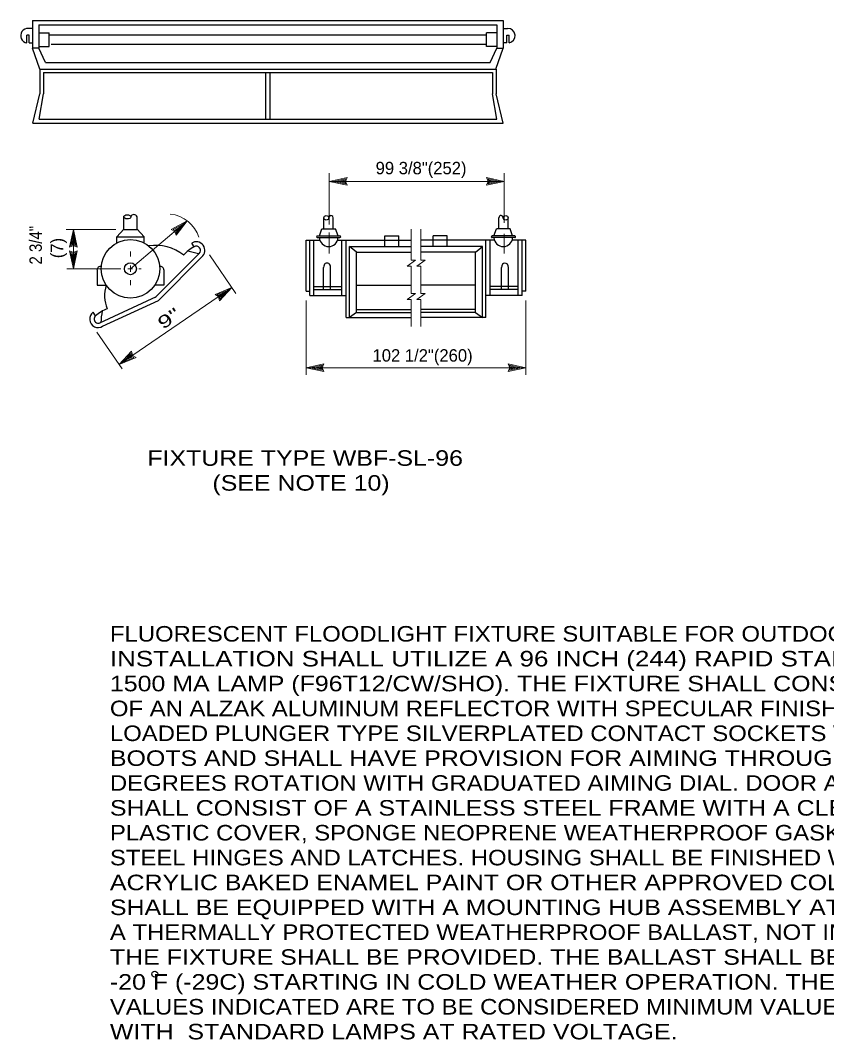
# Model space of a CAD drawing. Extents: x -39.6 to 16.1, y -17.6 to 34.
# Drawn here: x 2.33 to 8.82, y 15.9 to 24.1 of the extents above; entities that cross this region are included whole.
import ezdxf
from ezdxf.enums import TextEntityAlignment as Align

# ---------------------------------------------------------------- set-up
doc = ezdxf.new("R2010")
doc.units = 0
doc.header["$LTSCALE"] = 0.05
doc.layers.add('1', color=7, linetype='Continuous', lineweight=13)

msp = doc.modelspace()

# ---------------------------------------------------------------- linework, layer by layer
at = {"layer": '1', "lineweight": 25}
for p, q in [((2.43279, 24.02942), (2.39679, 24.02942)), ((2.43279, 24.09542), (6.22079, 24.09542)), ((2.43279, 24.09542), (2.43279, 23.87242)), ((2.48379, 24.05842), (6.16979, 24.05842)), ((6.22079, 24.09542), (6.22079, 23.87242)), ((6.22079, 24.02942), (6.25679, 24.02942)), ((2.38579, 23.91542), (2.38579, 23.97542)), ((2.48379, 23.99442), (2.56579, 23.99442)), ((6.08779, 23.97742), (2.56579, 23.97742)), ((6.16979, 23.99442), (6.08779, 23.99442)), ((6.26779, 23.91542), (6.26779, 23.97542)), ((2.40379, 23.91542), (2.43279, 23.91542)), ((2.49179, 23.70342), (2.43279, 23.87242)), ((2.53679, 23.75642), (2.48379, 23.87242)), ((6.08779, 23.90142), (2.58079, 23.90142)), ((6.11679, 23.75642), (6.16979, 23.87242)), ((6.16179, 23.70342), (6.22079, 23.87242)), ((6.24979, 23.91542), (6.22079, 23.91542)), ((2.48979, 23.70342), (2.48979, 23.50442)), ((2.49179, 23.70342), (6.16379, 23.70342)), ((2.53679, 23.75642), (6.11679, 23.75642)), ((6.16379, 23.70342), (6.16379, 23.50442)), ((2.51979, 23.67542), (6.13379, 23.67542)), ((2.51979, 23.67542), (2.51979, 23.50442)), ((4.30979, 23.30042), (4.30979, 23.67542)), ((4.34579, 23.30042), (4.34579, 23.67542)), ((6.13379, 23.67542), (6.13379, 23.50442)), ((2.43379, 23.26742), (2.48979, 23.50442)), ((2.48479, 23.30042), (2.51979, 23.50442)), ((6.21979, 23.26742), (6.16379, 23.50442)), ((2.43379, 23.26742), (6.21979, 23.26742)), ((4.77679, 22.41842), (4.77679, 22.50742)), ((4.85179, 22.41842), (4.85179, 22.50742)), ((6.18579, 22.41842), (6.18579, 22.50742)), ((6.26079, 22.41842), (6.26079, 22.50742)), ((3.16479, 22.41442), (3.27379, 22.41442)), ((4.74079, 22.36142), (4.75979, 22.41842)), ((4.75979, 22.41842), (4.87179, 22.41842)), ((4.89179, 22.36142), (4.87179, 22.41842)), ((6.14579, 22.36142), (6.16579, 22.41842)), ((6.27779, 22.41842), (6.16579, 22.41842)), ((6.29679, 22.36142), (6.27779, 22.41842)), ((3.10979, 22.35542), (3.32979, 22.35542)), ((3.73379, 22.27442), (3.71379, 22.30342)), ((4.63379, 21.91742), (4.63379, 22.32842)), ((4.63379, 22.32842), (4.74079, 22.32842)), ((4.66479, 21.88142), (4.66479, 22.32842)), ((4.69579, 21.88142), (4.69579, 22.32842)), ((4.72379, 22.36142), (4.90679, 22.36142)), ((4.72379, 22.34842), (4.90679, 22.34842)), ((4.88579, 22.32842), (5.47979, 22.32842)), ((4.92279, 21.88142), (4.92279, 22.33042)), ((4.95679, 21.70442), (4.95679, 22.33042)), ((5.26879, 22.27742), (5.26879, 22.36142)), ((5.26879, 22.36142), (5.38079, 22.36142)), ((5.38079, 22.27742), (5.38079, 22.36142)), ((6.15179, 22.32842), (5.55779, 22.32842)), ((5.65679, 22.27742), (5.65679, 22.36142)), ((5.76879, 22.36142), (5.65679, 22.36142)), ((5.76879, 22.27742), (5.76879, 22.36142)), ((6.08079, 21.70442), (6.08079, 22.33042)), ((6.11479, 21.88142), (6.11479, 22.33042)), ((6.31379, 22.36142), (6.13079, 22.36142)), ((6.31379, 22.34842), (6.13079, 22.34842)), ((6.40379, 22.32842), (6.29679, 22.32842)), ((6.34179, 21.88142), (6.34179, 22.32842)), ((6.37279, 21.88142), (6.37279, 22.32842)), ((6.40379, 21.91742), (6.40379, 22.32842)), ((3.77479, 22.22242), (3.41979, 21.86642)), ((5.03979, 22.23042), (4.98379, 22.27742)), ((5.99779, 22.23042), (6.05379, 22.27742)), ((3.79479, 22.19242), (3.44479, 21.84242)), ((4.77479, 21.93142), (4.77479, 22.10842)), ((4.83079, 21.93142), (4.83079, 22.10842)), ((6.20679, 21.93142), (6.20679, 22.10842)), ((6.26279, 21.93142), (6.26279, 22.10842)), ((4.63379, 21.91742), (4.66479, 21.91742)), ((4.69579, 21.95442), (4.92279, 21.95442)), ((4.69579, 21.93142), (4.92279, 21.93142)), ((5.03979, 21.96542), (5.47979, 21.96542)), ((5.99779, 21.96542), (5.55779, 21.96542)), ((6.34179, 21.95442), (6.11479, 21.95442)), ((6.34179, 21.93142), (6.11479, 21.93142)), ((6.40379, 21.91742), (6.37279, 21.91742)), ((2.97379, 21.66242), (3.42979, 21.87342)), ((2.99579, 21.63442), (3.44479, 21.84242)), ((4.66479, 21.88142), (4.95679, 21.88142)), ((6.37279, 21.88142), (6.08079, 21.88142)), ((2.93979, 21.71842), (2.91979, 21.74742)), ((5.03979, 21.74642), (4.98379, 21.70442)), ((5.03979, 21.76942), (5.47979, 21.76942)), ((5.03979, 21.74642), (5.47979, 21.74642)), ((5.99779, 21.76942), (5.55779, 21.76942)), ((5.99779, 21.74642), (5.55779, 21.74642)), ((5.99779, 21.74642), (6.05379, 21.70442)), ((4.95679, 21.70442), (5.47979, 21.70442)), ((6.08079, 21.70442), (5.55779, 21.70442))]:
    msp.add_line(p, q, dxfattribs=at)
at = {"layer": '1'}
for p, q in [((4.82079, 22.45442), (4.82079, 22.86642)), ((4.82079, 22.80042), (4.96479, 22.83142)), ((4.82079, 22.80042), (6.22979, 22.80042)), ((4.82079, 22.80042), (4.96479, 22.76942)), ((4.85779, 22.80042), (4.95179, 22.82042)), ((4.85779, 22.80042), (4.95179, 22.78042)), ((4.89379, 22.80042), (4.93879, 22.81042)), ((4.89379, 22.80042), (4.93879, 22.79142)), ((4.93879, 22.81042), (4.93479, 22.80042)), ((4.93479, 22.80042), (4.93879, 22.79142)), ((4.95179, 22.82042), (4.94279, 22.80042)), ((4.94279, 22.80042), (4.95179, 22.78042)), ((6.22979, 22.80042), (6.08579, 22.83142)), ((6.22979, 22.80042), (6.08579, 22.76942)), ((6.19279, 22.80042), (6.09879, 22.82042)), ((6.10779, 22.80042), (6.09879, 22.82042)), ((6.19279, 22.80042), (6.09879, 22.78042)), ((6.09879, 22.78042), (6.10779, 22.80042)), ((6.15679, 22.80042), (6.11179, 22.80942)), ((6.11579, 22.80042), (6.11179, 22.80942)), ((6.15679, 22.80042), (6.11179, 22.79042)), ((6.11179, 22.79042), (6.11579, 22.80042)), ((6.22979, 22.46742), (6.22979, 22.86642)), ((3.21979, 22.09742), (3.67779, 22.48242)), ((3.67779, 22.48242), (3.54779, 22.41342)), ((3.67779, 22.48242), (3.58779, 22.36642)), ((3.10279, 22.41442), (2.70379, 22.41442)), ((2.76079, 22.41442), (2.72979, 22.27042)), ((2.76079, 22.09742), (2.76079, 22.41442)), ((2.76079, 22.41442), (2.79179, 22.27042)), ((3.64979, 22.45842), (3.56479, 22.41342)), ((3.58479, 22.40342), (3.56479, 22.41342)), ((3.62179, 22.43542), (3.58179, 22.41342)), ((3.59079, 22.40942), (3.58179, 22.41342)), ((3.59079, 22.38242), (3.58479, 22.40342)), ((3.64979, 22.45842), (3.59079, 22.38242)), ((3.59379, 22.39842), (3.59079, 22.40942)), ((3.62179, 22.43542), (3.59379, 22.39842)), ((4.82079, 22.21942), (4.82079, 22.38842)), ((5.47979, 22.16642), (5.47979, 22.41642)), ((5.55779, 22.16642), (5.55779, 22.41642)), ((2.76079, 22.37742), (2.74079, 22.28342)), ((2.76079, 22.34142), (2.75179, 22.29642)), ((2.76079, 22.37742), (2.78079, 22.28342)), ((2.76079, 22.34142), (2.77079, 22.29642)), ((6.22979, 22.21942), (6.22979, 22.37942)), ((2.76079, 22.09742), (2.72979, 22.24142)), ((2.76079, 22.29242), (2.74079, 22.28342)), ((2.76079, 22.13442), (2.74079, 22.22842)), ((2.74079, 22.22842), (2.76079, 22.21942)), ((2.76079, 22.30042), (2.75179, 22.29642)), ((2.77079, 22.29642), (2.76079, 22.30042)), ((2.78079, 22.28342), (2.76079, 22.29242)), ((2.76079, 22.09742), (2.79179, 22.24142)), ((2.76079, 22.13442), (2.78079, 22.22842)), ((2.76079, 22.21942), (2.78079, 22.22842)), ((3.21979, 22.19542), (3.21979, 22.23542)), ((2.76079, 22.17042), (2.75079, 22.21542)), ((2.75079, 22.21542), (2.76079, 22.21142)), ((2.76079, 22.17042), (2.76979, 22.21542)), ((2.76079, 22.21142), (2.76979, 22.21542)), ((3.85779, 22.20842), (4.06979, 21.89842)), ((5.44679, 22.11842), (5.51379, 22.16642)), ((5.47979, 22.16642), (5.51379, 22.16642)), ((5.52479, 22.11842), (5.59179, 22.16642)), ((5.55779, 22.16642), (5.59179, 22.16642)), ((3.14179, 22.09742), (2.70779, 22.09742)), ((3.23579, 22.09742), (3.19979, 22.09742)), ((3.21979, 22.07142), (3.21979, 22.12442)), ((3.30579, 22.09742), (3.28879, 22.09742)), ((5.44679, 22.11842), (5.47979, 22.11842)), ((5.47979, 21.89942), (5.47979, 22.11842)), ((5.52479, 22.11842), (5.55779, 22.11842)), ((5.55779, 21.89942), (5.55779, 22.11842)), ((3.21979, 21.96542), (3.21979, 22.00542)), ((3.12879, 21.32642), (4.03679, 21.94642)), ((4.03679, 21.94642), (3.90079, 21.89042)), ((4.00579, 21.92542), (3.91779, 21.88942)), ((3.97679, 21.90542), (3.93379, 21.88742)), ((4.03679, 21.94642), (3.93579, 21.83942)), ((4.00579, 21.92542), (3.93979, 21.85642)), ((3.97679, 21.90542), (3.94479, 21.87142)), ((5.44679, 21.85142), (5.51379, 21.89942)), ((5.47979, 21.89942), (5.51379, 21.89942)), ((5.52479, 21.85142), (5.59179, 21.89942)), ((5.55779, 21.89942), (5.59179, 21.89942)), ((3.93579, 21.87742), (3.91779, 21.88942)), ((3.94279, 21.88242), (3.93379, 21.88742)), ((3.93979, 21.85642), (3.93579, 21.87742)), ((3.94479, 21.87142), (3.94279, 21.88242)), ((4.63379, 21.84242), (4.63379, 21.24442)), ((5.44679, 21.85142), (5.47979, 21.85142)), ((5.47979, 21.63242), (5.47979, 21.85142)), ((5.52479, 21.85142), (5.55779, 21.85142)), ((5.55779, 21.63242), (5.55779, 21.85142)), ((6.40379, 21.84242), (6.40379, 21.24442)), ((2.94979, 21.58842), (3.15279, 21.29142)), ((3.12879, 21.32642), (3.22979, 21.43342)), ((3.15979, 21.34742), (3.22579, 21.41642)), ((3.18879, 21.36742), (3.22079, 21.40142)), ((3.22079, 21.40142), (3.22279, 21.39042)), ((3.22579, 21.41642), (3.22979, 21.39542)), ((3.12879, 21.32642), (3.26479, 21.38242)), ((3.15979, 21.34742), (3.24779, 21.38342)), ((3.18879, 21.36742), (3.23179, 21.38542)), ((3.22279, 21.39042), (3.23179, 21.38542)), ((3.22979, 21.39542), (3.24779, 21.38342)), ((4.63379, 21.30142), (4.77779, 21.33242)), ((4.67079, 21.30142), (4.76479, 21.32142)), ((4.76479, 21.32142), (4.75579, 21.30142)), ((6.40379, 21.30142), (6.25979, 21.33242)), ((6.36679, 21.30142), (6.27279, 21.32142)), ((6.28179, 21.30142), (6.27279, 21.32142)), ((4.63379, 21.30142), (6.40379, 21.30142)), ((4.63379, 21.30142), (4.77779, 21.27042)), ((4.67079, 21.30142), (4.76479, 21.28142)), ((4.70679, 21.30142), (4.75179, 21.31142)), ((4.70679, 21.30142), (4.75179, 21.29242)), ((4.75179, 21.31142), (4.74779, 21.30142)), ((4.74779, 21.30142), (4.75179, 21.29242)), ((4.75579, 21.30142), (4.76479, 21.28142)), ((6.40379, 21.30142), (6.25979, 21.27042)), ((6.36679, 21.30142), (6.27279, 21.28142)), ((6.27279, 21.28142), (6.28179, 21.30142)), ((6.33079, 21.30142), (6.28579, 21.31042)), ((6.28979, 21.30142), (6.28579, 21.31042)), ((6.33079, 21.30142), (6.28579, 21.29142)), ((6.28579, 21.29142), (6.28979, 21.30142))]:
    msp.add_line(p, q, dxfattribs=at)
at = {"layer": '1', "lineweight": 25}
for points in [[(2.48379, 24.05842), (2.48379, 23.87242), (2.43279, 23.87242)], [(6.16979, 24.05842), (6.16979, 23.87242), (6.22079, 23.87242)], [(2.40379, 23.91542), (2.40379, 23.97542), (2.38579, 23.97542)], [(2.48379, 23.88642), (2.56579, 23.88642), (2.56579, 23.99442)], [(6.16979, 23.88642), (6.08779, 23.88642), (6.08779, 23.99442)], [(6.24979, 23.91542), (6.24979, 23.97542), (6.26779, 23.97542)], [(2.48479, 23.30042), (6.16879, 23.30042), (6.13379, 23.50442)], [(3.10979, 22.30542), (3.10979, 22.35542), (3.16579, 22.41542), (3.16579, 22.51542)], [(3.32979, 22.30542), (3.32979, 22.35542), (3.27379, 22.41542), (3.27379, 22.51542)], [(4.98379, 21.70442), (4.98379, 22.27742), (5.47979, 22.27742)], [(5.03979, 21.74642), (5.03979, 22.23042), (5.47979, 22.23042)], [(6.05379, 21.70442), (6.05379, 22.27742), (5.55779, 22.27742)], [(5.99779, 21.74642), (5.99779, 22.23042), (5.55779, 22.23042)], [(2.95079, 22.08842), (2.95079, 21.96442), (3.02479, 21.96442)], [(3.48879, 22.08842), (3.48879, 21.96442), (3.41479, 21.96442)]]:
    msp.add_lwpolyline(points, dxfattribs=at)
at = {"layer": '1'}
for points in [[(4.96479, 22.83142), (4.95079, 22.80042), (4.96479, 22.76942)], [(6.08579, 22.76942), (6.09979, 22.80042), (6.08579, 22.83142)], [(3.58779, 22.36642), (3.57779, 22.39842), (3.54779, 22.41342)], [(2.79179, 22.27042), (2.76079, 22.28442), (2.72979, 22.27042)], [(2.72979, 22.24142), (2.76079, 22.22742), (2.79179, 22.24142)], [(3.93579, 21.83942), (3.92979, 21.87342), (3.90079, 21.89042)], [(3.22979, 21.43342), (3.23579, 21.39942), (3.26479, 21.38242)], [(4.77779, 21.33242), (4.76379, 21.30142), (4.77779, 21.27042)], [(6.25979, 21.27042), (6.27379, 21.30142), (6.25979, 21.33242)]]:
    msp.add_lwpolyline(points, dxfattribs=at)
at = {"layer": '1', "lineweight": 25}
for centre, radius in [((3.21979, 22.09742), 0.23567), ((3.21979, 22.09742), 0.04804), ((3.41579, 16.42342), 0.024)]:
    msp.add_circle(centre, radius, dxfattribs=at)
for centre, radius, start, end in [((3.24845, 22.50678), 0.02677, 18.82841, 163.4182), ((4.81584, 22.35119), 0.0751, 182.11351, 356.35869), ((6.22174, 22.35119), 0.0751, 183.64131, 357.88649), ((3.42373, 21.92785), 0.35813, 51.06477, 99.14828), ((3.86715, 22.01905), 0.28818, 117.58646, 139.405), ((3.52542, 21.40997), 0.84296, 73.26123, 79.41915), ((2.97784, 22.08809), 0.02723, 75.20264, 179.31411), ((3.46175, 22.08809), 0.02723, 0.68589, 104.79736), ((3.2857, 21.88079), 0.27398, 162.22843, 202.61911), ((3.13416, 21.50566), 0.28818, 110.595, 132.41354), ((3.82338, 21.61846), 0.84296, 170.58085, 176.73877)]:
    msp.add_arc(centre, radius, start, end, dxfattribs=at)
at = {"layer": '1'}
msp.add_arc((3.50886, 22.2618), 0.27746, 18.62635, 83.39167, dxfattribs=at)
at = {"layer": '1', "lineweight": 25}
for centre, major_axis, ratio, start_param, end_param in [((2.39129, 23.97242), (0.0055, 0.057), 0.954258, 0, 3.1415927), ((6.26229, 23.97242), (-0.0055, 0.057), 0.954258, 3.1415927, 6.2831853), ((4.83429, 22.50642), (0.00114, -0.02002), 0.87393, 1.5707963, 4.712389), ((6.20329, 22.50642), (0.00114, 0.02002), 0.87393, 4.712389, 7.8539816), ((3.75338, 22.24814), (-0.0401, 0.05503), 0.948527, 3.1415927, 6.2831853), ((4.72379, 22.35492), (0, -0.0065), 0.92582, 3.1415927, 6.2831853), ((4.90679, 22.35492), (0, 0.0065), 0.948683, 3.1415927, 6.2831853), ((6.13079, 22.35492), (0, 0.0065), 0.948683, 6.2831853, 9.424778), ((6.31379, 22.35492), (0, -0.0065), 0.92582, 6.2831853, 9.424778), ((3.75338, 22.24814), (-0.01938, 0.0266), 0.893523, 3.1415927, 6.2831853), ((4.80279, 22.10842), (0, -0.0352), 0.795395, 1.5707963, 4.712389), ((6.23479, 22.10842), (0, 0.0352), 0.795395, 4.712389, 7.8539816), ((2.95779, 21.69092), (-0.038, 0.0565), 0.948527, 6.2831853, 9.424778), ((2.95779, 21.69092), (-0.01837, 0.02731), 0.893523, 6.2831853, 9.424778)]:
    msp.add_ellipse(centre, major_axis=major_axis, ratio=ratio, start_param=start_param, end_param=end_param, dxfattribs=at)
for centre, major_axis, ratio in [((3.19429, 22.51492), (0.0285, -0.0005), 0.581778), ((4.79679, 22.50742), (0.02, 0), 0.910299), ((6.24079, 22.50742), (-0.02, 0), 0.910299)]:
    msp.add_ellipse(centre, major_axis=major_axis, ratio=ratio, dxfattribs=at)

# ---------------------------------------------------------------- texts
at = {"layer": '1'}
for s, p in [('99 3/8"(252)', (5.55979, 22.85742)), ('102 1/2"(260)', (5.57179, 21.35042))]:
    msp.add_text(s, height=0.1, dxfattribs=at).set_placement(p, align=Align.CENTER)
for s, rotation, width, p in [('2 3/4"', 90, 0.9, (2.50679, 22.28692)), ('9"', 34.371, 1.5, (3.55715, 21.65711))]:
    msp.add_text(s, height=0.1, rotation=rotation, dxfattribs=dict(at, width=width)).set_placement(p, align=Align.CENTER)
msp.add_text('(7)', height=0.1, rotation=90, dxfattribs=at).set_placement((2.67879, 22.26392), align=Align.CENTER)
at = {"layer": '1', "width": 1.2}
for s, p in [('FIXTURE TYPE WBF-SL-96', (4.62629, 20.51242)), ('(SEE NOTE 10)', (4.59329, 20.31242))]:
    msp.add_text(s, height=0.125, dxfattribs=at).set_placement(p, align=Align.CENTER)
at = {"layer": '1'}
for s, width, p in [('FLUORESCENT FLOODLIGHT FIXTURE SUITABLE FOR OUTDOOR', 1.15, (3.05479, 19.09842)), ('INSTALLATION SHALL UTILIZE A 96 INCH (244) RAPID START', 1.25, (3.05479, 18.89842)), ('1500 MA LAMP (F96T12/CW/SHO). THE FIXTURE SHALL CONSIST', 1.2, (3.05479, 18.69842)), ('OF AN ALZAK ALUMINUM REFLECTOR WITH SPECULAR FINISH, SPRING', 1.15, (3.05479, 18.49842)), ('LOADED PLUNGER TYPE SILVERPLATED CONTACT SOCKETS WITH NEOPRENE', 1.15, (3.05479, 18.29842)), ('BOOTS AND SHALL HAVE PROVISION FOR AIMING THROUGHOUT 360', 1.2, (3.05479, 18.09842)), ('DEGREES ROTATION WITH GRADUATED AIMING DIAL. DOOR ASSEMBLY', 1.15, (3.05479, 17.89842)), ('SHALL CONSIST OF A STAINLESS STEEL FRAME WITH A CLEAR ACRYLIC', 1.2, (3.05479, 17.69842)), ('PLASTIC COVER, SPONGE NEOPRENE WEATHERPROOF GASKET WITH STAINLESS', 1.15, (3.05479, 17.49842)), ('STEEL HINGES AND LATCHES. HOUSING SHALL BE FINISHED WITH GREEN', 1.15, (3.05479, 17.29842)), ('ACRYLIC BAKED ENAMEL PAINT OR OTHER APPROVED COLOR. THE FIXTURE', 1.2, (3.05479, 17.09842)), ('SHALL BE EQUIPPED WITH A MOUNTING HUB ASSEMBLY AT EACH END.', 1.2, (3.05479, 16.89842)), ('A THERMALLY PROTECTED WEATHERPROOF BALLAST, NOT INTEGRAL WITH', 1.15, (3.05479, 16.69842)), ('THE FIXTURE SHALL BE PROVIDED. THE BALLAST SHALL BE RATED FOR', 1.2, (3.05479, 16.49842)), ('-20 F (-29C) STARTING IN COLD WEATHER OPERATION. THE CANDLEPOWER', 1.2, (3.05479, 16.29842)), ('VALUES INDICATED ARE TO BE CONSIDERED MINIMUM VALUES OBTAINED', 1.15, (3.05479, 16.09842)), ('WITH  STANDARD LAMPS AT RATED VOLTAGE.', 1.2, (3.05479, 15.89842))]:
    msp.add_text(s, height=0.125, dxfattribs=dict(at, width=width)).set_placement(p)

doc.saveas('drawing.dxf')
